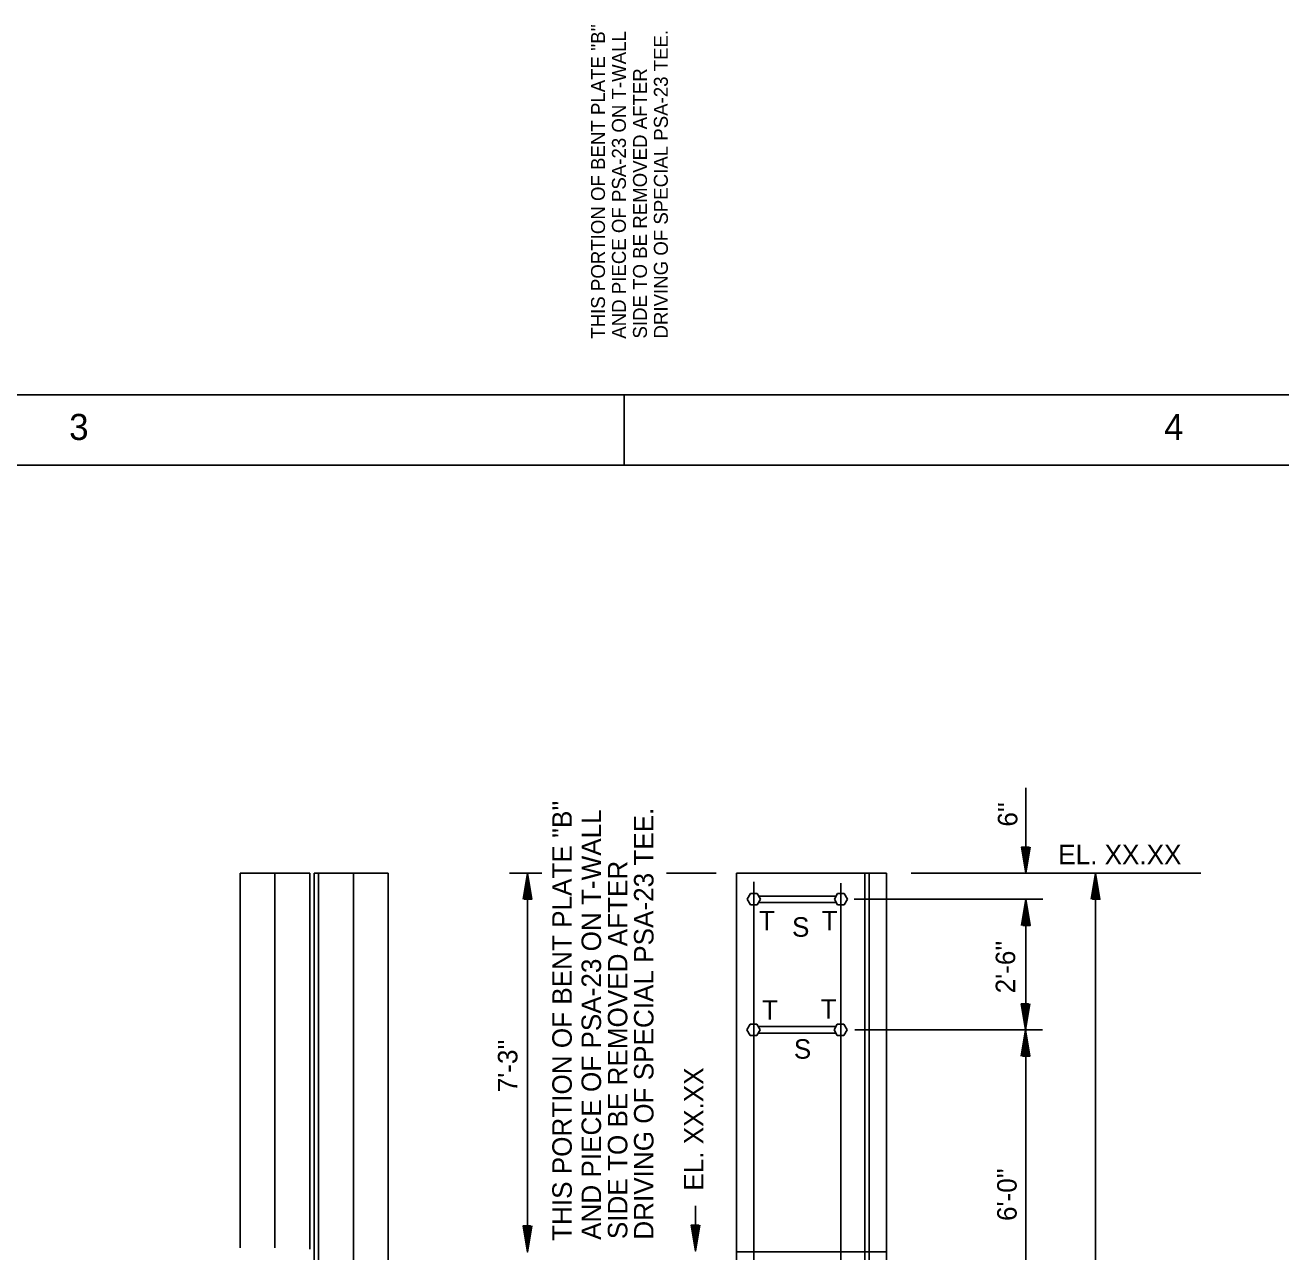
# Model space of a CAD drawing. Extents: x 22369.6 to 22384.3, y 22369.6 to 22381.8.
# Drawn here: x 22376.535 to 22379.54, y 22378.907 to 22381.842 of the extents above; entities that cross this region are included whole.
import ezdxf

# ---------------------------------------------------------------- set-up
doc = ezdxf.new("R2010")
doc.units = 0
for name, color, linetype in [('Level 1', 7, 'Continuous'), ('Level 10', 7, 'Continuous'), ('Level 2', 7, 'Continuous'), ('Level 4', 7, 'Continuous'), ('Level 7', 7, 'Continuous'), ('Level 9', 7, 'Continuous')]:
    doc.layers.add(name, color=color, linetype=linetype)

msp = doc.modelspace()

# ---------------------------------------------------------------- linework, layer by layer
at = {"layer": 'Level 1'}
for p, q in [((22378.9295, 22380.0174), (22378.9295, 22379.8132)), ((22378.9295, 22379.8305), (22378.9295, 22379.8305)), ((22377.6939, 22379.8132), (22377.771, 22379.8132)), ((22377.7368, 22379.8132), (22377.7368, 22379.8132)), ((22377.7368, 22379.8132), (22377.7368, 22378.9069)), ((22377.7368, 22379.7958), (22377.7368, 22379.7958)), ((22378.1881, 22379.8132), (22378.0694, 22379.8132)), ((22378.6547, 22379.8132), (22379.3476, 22379.8132)), ((22378.9295, 22379.8132), (22378.9295, 22379.8132)), ((22379.0962, 22379.8132), (22379.0962, 22379.8132)), ((22379.0962, 22376.9382), (22379.0962, 22379.8132)), ((22379.0962, 22379.7958), (22379.0962, 22379.7958)), ((22378.2627, 22379.7507), (22378.2706, 22379.7643)), ((22378.2706, 22379.7643), (22378.2863, 22379.7643)), ((22378.2784, 22379.7925), (22378.2784, 22377.0773)), ((22378.2942, 22379.7507), (22378.2863, 22379.7643)), ((22378.4711, 22379.7507), (22378.4789, 22379.7643)), ((22378.4789, 22379.7643), (22378.4946, 22379.7643)), ((22378.4868, 22379.789), (22378.4868, 22377.1039)), ((22378.5025, 22379.7507), (22378.4946, 22379.7643)), ((22378.2627, 22379.7507), (22378.2706, 22379.737)), ((22378.2706, 22379.737), (22378.2863, 22379.737)), ((22378.2942, 22379.7507), (22378.2863, 22379.737)), ((22378.2896, 22379.7585), (22378.4756, 22379.7585)), ((22378.2896, 22379.7429), (22378.4756, 22379.7429)), ((22378.4711, 22379.7507), (22378.4789, 22379.737)), ((22378.4789, 22379.737), (22378.4946, 22379.737)), ((22378.5025, 22379.7507), (22378.4946, 22379.737)), ((22378.5182, 22379.7507), (22378.9701, 22379.7507)), ((22378.9295, 22379.7507), (22378.9295, 22379.7507)), ((22378.9295, 22379.4382), (22378.9295, 22379.7507)), ((22378.9295, 22379.7333), (22378.9295, 22379.7333)), ((22378.2619, 22379.4382), (22378.2698, 22379.4518)), ((22378.2619, 22379.4382), (22378.2698, 22379.4245)), ((22378.2698, 22379.4518), (22378.2855, 22379.4518)), ((22378.2933, 22379.4382), (22378.2855, 22379.4518)), ((22378.2933, 22379.4382), (22378.2855, 22379.4245)), ((22378.2888, 22379.446), (22378.4748, 22379.446)), ((22378.4703, 22379.4382), (22378.4781, 22379.4518)), ((22378.4703, 22379.4382), (22378.4781, 22379.4245)), ((22378.4781, 22379.4518), (22378.4938, 22379.4518)), ((22378.5017, 22379.4382), (22378.4938, 22379.4518)), ((22378.5017, 22379.4382), (22378.4938, 22379.4245)), ((22378.5203, 22379.4382), (22378.9693, 22379.4382)), ((22378.9287, 22379.4555), (22378.9287, 22379.4555)), ((22378.9287, 22379.4382), (22378.9287, 22379.4382)), ((22378.9287, 22379.4382), (22378.9287, 22379.4382)), ((22378.9295, 22378.6882), (22378.9295, 22379.4382)), ((22378.2698, 22379.4245), (22378.2855, 22379.4245)), ((22378.2888, 22379.4304), (22378.4748, 22379.4304)), ((22378.4781, 22379.4245), (22378.4938, 22379.4245)), ((22378.9287, 22379.4208), (22378.9287, 22379.4208)), ((22378.1392, 22378.9091), (22378.1392, 22379.0173)), ((22377.7368, 22378.9243), (22377.7368, 22378.9243)), ((22378.1392, 22378.9264), (22378.1392, 22378.9264)), ((22378.1392, 22378.9091), (22378.1392, 22378.9091))]:
    msp.add_line(p, q, dxfattribs=at)
msp.add_lwpolyline([(22369.6213, 22380.9573), (22384.2881, 22380.9573), (22384.2881, 22369.6213), (22369.6213, 22369.6213)], close=True, dxfattribs=at)
for points in [[(22378.9398, 22379.8755), (22378.9295, 22379.8132), (22378.9192, 22379.8755), (22378.9368, 22379.8755), (22378.9295, 22379.8305), (22378.9225, 22379.8728), (22378.9338, 22379.8728), (22378.9295, 22379.8472), (22378.9258, 22379.8702), (22378.9305, 22379.8702), (22378.9295, 22379.8645)], [(22377.7264, 22379.7508), (22377.7368, 22379.8132), (22377.7471, 22379.7508), (22377.7294, 22379.7508), (22377.7368, 22379.7958), (22377.7438, 22379.7535), (22377.7324, 22379.7535), (22377.7368, 22379.7792), (22377.7404, 22379.7562), (22377.7358, 22379.7562), (22377.7368, 22379.7618)], [(22379.0858, 22379.7508), (22379.0962, 22379.8132), (22379.1065, 22379.7508), (22379.0888, 22379.7508), (22379.0962, 22379.7958), (22379.1032, 22379.7535), (22379.0918, 22379.7535), (22379.0962, 22379.7792), (22379.0998, 22379.7562), (22379.0952, 22379.7562), (22379.0962, 22379.7618)], [(22378.9192, 22379.6883), (22378.9295, 22379.7507), (22378.9398, 22379.6883), (22378.9222, 22379.6883), (22378.9295, 22379.7333), (22378.9365, 22379.691), (22378.9252, 22379.691), (22378.9295, 22379.7167), (22378.9332, 22379.6937), (22378.9285, 22379.6937), (22378.9295, 22379.6993)], [(22378.939, 22379.5005), (22378.9287, 22379.4382), (22378.9183, 22379.5005), (22378.936, 22379.5005), (22378.9287, 22379.4555), (22378.9217, 22379.4978), (22378.933, 22379.4978), (22378.9287, 22379.4722), (22378.925, 22379.4952), (22378.9297, 22379.4952), (22378.9287, 22379.4895)], [(22378.9183, 22379.3758), (22378.9287, 22379.4382), (22378.939, 22379.3758), (22378.9213, 22379.3758), (22378.9287, 22379.4208), (22378.9357, 22379.3785), (22378.9243, 22379.3785), (22378.9287, 22379.4042), (22378.9323, 22379.3812), (22378.9277, 22379.3812), (22378.9287, 22379.3868)], [(22377.7471, 22378.9693), (22377.7368, 22378.9069), (22377.7264, 22378.9693), (22377.7441, 22378.9693), (22377.7368, 22378.9243), (22377.7298, 22378.9666), (22377.7411, 22378.9666), (22377.7368, 22378.9409), (22377.7331, 22378.9639), (22377.7378, 22378.9639), (22377.7368, 22378.9583)], [(22378.1495, 22378.9714), (22378.1392, 22378.9091), (22378.1288, 22378.9714), (22378.1465, 22378.9714), (22378.1392, 22378.9264), (22378.1322, 22378.9688), (22378.1435, 22378.9688), (22378.1392, 22378.9431), (22378.1355, 22378.9661), (22378.1402, 22378.9661), (22378.1392, 22378.9604)]]:
    msp.add_lwpolyline(points, dxfattribs=at)
at = {"layer": 'Level 10'}
msp.add_line((22377.9681, 22380.7893), (22377.9681, 22380.9573), dxfattribs=at)
at = {"layer": 'Level 2'}
for p, q in [((22377.0493, 22378.9171), (22377.0493, 22379.8132)), ((22377.0493, 22379.8132), (22377.2159, 22379.8132)), ((22377.1326, 22378.9171), (22377.1326, 22379.8132)), ((22377.2159, 22378.9137), (22377.2159, 22379.8132)), ((22378.2368, 22378.9077), (22378.5962, 22378.9077))]:
    msp.add_line(p, q, dxfattribs=at)
at = {"layer": 'Level 7'}
for p, q in [((22377.2264, 22379.8132), (22377.4034, 22379.8132)), ((22377.2264, 22376.9382), (22377.2264, 22379.8132)), ((22377.2368, 22376.9382), (22377.2368, 22379.8132)), ((22377.3201, 22376.9382), (22377.3201, 22379.8132)), ((22377.4034, 22376.9382), (22377.4034, 22379.8132)), ((22378.2368, 22376.9382), (22378.2368, 22379.8132)), ((22378.2368, 22379.8132), (22378.5962, 22379.8132)), ((22378.5441, 22376.9382), (22378.5441, 22379.8132)), ((22378.5545, 22376.9382), (22378.5545, 22379.8132)), ((22378.5962, 22376.9382), (22378.5962, 22379.8132))]:
    msp.add_line(p, q, dxfattribs=at)
at = {"layer": 'Level 9'}
msp.add_line((22370.1213, 22380.7893), (22383.2041, 22380.7893), dxfattribs=at)

# ---------------------------------------------------------------- texts
at = {"layer": 'Level 1'}
for s, p in [('3', (22376.6401, 22380.8493)), ('4', (22379.2601, 22380.8493))]:
    msp.add_text(s, height=0.0624, dxfattribs=at).set_placement(p)
at = {"layer": 'Level 4'}
for s, height, p in [("THIS PORTION OF BENT PLATE ''B''", 0.033337, (22377.9222, 22381.0914)), ('AND PIECE OF PSA-23 ON T-WALL', 0.033337, (22377.9722, 22381.0914)), ('DRIVING OF SPECIAL PSA-23 TEE.', 0.033337, (22378.0726, 22381.0919)), ('SIDE TO BE REMOVED AFTER', 0.033337, (22378.0226, 22381.0919)), ("THIS PORTION OF BENT PLATE ''B''", 0.046663, (22377.8428, 22378.9335)), ("6''", 0.04666, (22378.909, 22379.9245)), ('AND PIECE OF PSA-23 ON T-WALL', 0.046663, (22377.9128, 22378.936)), ('DRIVING OF SPECIAL PSA-23 TEE.', 0.046663, (22378.0383, 22378.9365)), ('SIDE TO BE REMOVED AFTER', 0.046663, (22377.9758, 22378.9378)), ("2'-6''", 0.04666, (22378.9038, 22379.5257)), ("7'-3''", 0.04666, (22377.7127, 22379.2892)), ('EL. XX.XX', 0.04666, (22378.1578, 22379.0537)), ("6'-0''", 0.04666, (22378.9073, 22378.9813))]:
    msp.add_text(s, height=height, rotation=90, dxfattribs=at).set_placement(p)
for s, height, p in [('EL. XX.XX', 0.04666, (22379.0068, 22379.8343)), ('T', 0.0467, (22378.2907, 22379.6762)), ('S', 0.0467, (22378.3697, 22379.6611)), ('T', 0.0467, (22378.4405, 22379.6762)), ('T', 0.0467, (22378.2978, 22379.4625)), ('T', 0.0467, (22378.4382, 22379.4648)), ('S', 0.0467, (22378.3741, 22379.3693))]:
    msp.add_text(s, height=height, dxfattribs=at).set_placement(p)

doc.saveas('drawing.dxf')
